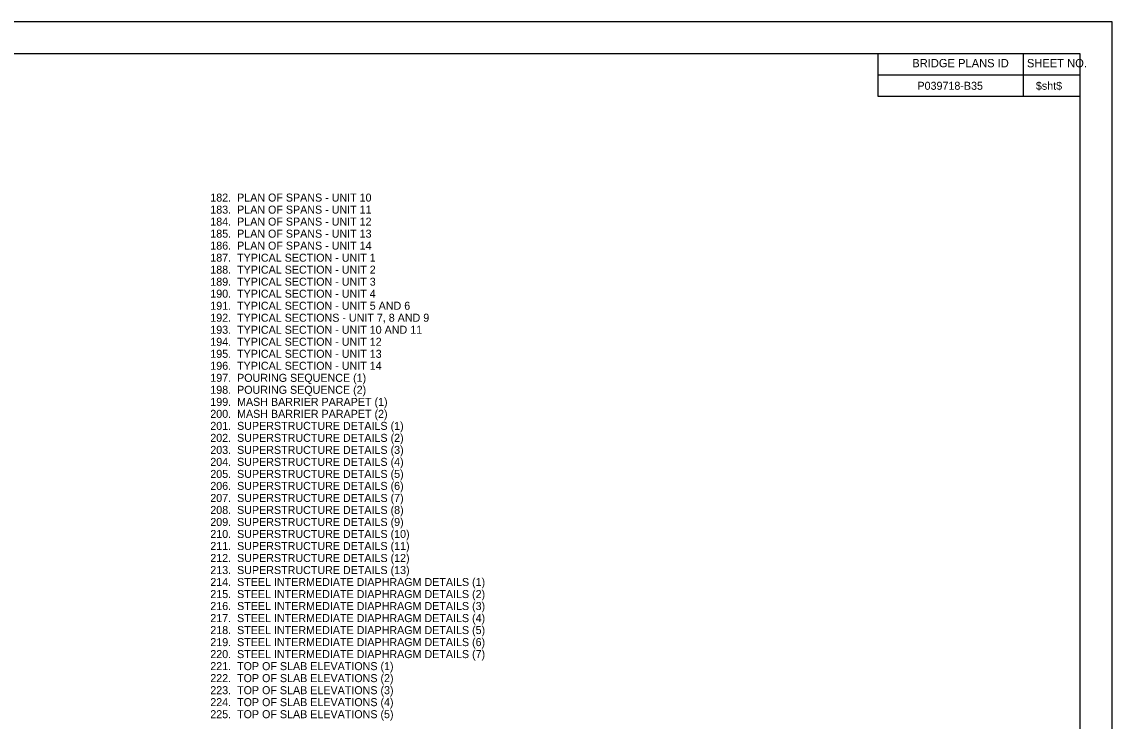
# Model space of a CAD drawing. Extents: x -125.5 to -89.4, y -5.1 to 16.9.
# Drawn here: x -106.56 to -89.53, y 6.02 to 16.93 of the extents above; entities that cross this region are included whole.
import ezdxf

# ---------------------------------------------------------------- set-up
doc = ezdxf.new("R2010")
doc.units = 0
for name, color, linetype in [('BR_BORDER LINES', 7, 'Continuous'), ('BR_TEXT', 7, 'Continuous'), ('Level 31', 7, 'Continuous')]:
    doc.layers.add(name, color=color, linetype=linetype)

msp = doc.modelspace()

# ---------------------------------------------------------------- linework, layer by layer
at = {"layer": 'BR_BORDER LINES'}
for p, q in [((-90.033, 16.434), (-123.699, 16.434)), ((-93.186, 15.767), (-93.186, 16.434)), ((-90.919, 15.767), (-90.919, 16.434)), ((-90.033, -4.566), (-90.033, 16.434)), ((-93.186, 16.104), (-90.033, 16.104)), ((-90.919, 16.104), (-90.033, 16.104)), ((-90.033, 15.767), (-93.186, 15.767))]:
    msp.add_line(p, q, dxfattribs=at)
at = {"layer": 'Level 31'}
msp.add_lwpolyline([(-125.533, -5.066), (-89.533, -5.066), (-89.533, 16.934), (-125.533, 16.934)], close=True, dxfattribs=at)

# ---------------------------------------------------------------- texts
at = {"layer": 'BR_TEXT'}
for s, height, p in [('BRIDGE PLANS ID', 0.13, (-92.654, 16.224)), ('SHEET NO.', 0.13, (-90.864, 16.224)), ('$sht$', 0.125, (-90.724, 15.873)), ('P039718-B35', 0.125, (-92.573, 15.873)), ('P039718-B35', 0.125, (-92.573, 15.873)), ('182.  PLAN OF SPANS - UNIT 10', 0.125, (-103.614, 14.128)), ('183.  PLAN OF SPANS - UNIT 11', 0.125, (-103.614, 13.94)), ('184.  PLAN OF SPANS - UNIT 12', 0.125, (-103.614, 13.753)), ('185.  PLAN OF SPANS - UNIT 13', 0.125, (-103.614, 13.565)), ('186.  PLAN OF SPANS - UNIT 14', 0.125, (-103.614, 13.378)), ('187.  TYPICAL SECTION - UNIT 1', 0.125, (-103.614, 13.19)), ('188.  TYPICAL SECTION - UNIT 2', 0.125, (-103.614, 13.003)), ('189.  TYPICAL SECTION - UNIT 3', 0.125, (-103.614, 12.815)), ('190.  TYPICAL SECTION - UNIT 4', 0.125, (-103.614, 12.628)), ('191.  TYPICAL SECTION - UNIT 5 AND 6', 0.125, (-103.614, 12.44)), ('192.  TYPICAL SECTIONS - UNIT 7, 8 AND 9', 0.125, (-103.614, 12.253)), ('193.  TYPICAL SECTION - UNIT 10 AND 11', 0.125, (-103.614, 12.065)), ('194.  TYPICAL SECTION - UNIT 12', 0.125, (-103.614, 11.878)), ('195.  TYPICAL SECTION - UNIT 13', 0.125, (-103.614, 11.69)), ('196.  TYPICAL SECTION - UNIT 14', 0.125, (-103.614, 11.503)), ('197.  POURING SEQUENCE (1)', 0.125, (-103.614, 11.315)), ('198.  POURING SEQUENCE (2)', 0.125, (-103.614, 11.128)), ('199.  MASH BARRIER PARAPET (1)', 0.125, (-103.614, 10.94)), ('200.  MASH BARRIER PARAPET (2)', 0.125, (-103.614, 10.753)), ('201.  SUPERSTRUCTURE DETAILS (1)', 0.125, (-103.614, 10.565)), ('202.  SUPERSTRUCTURE DETAILS (2)', 0.125, (-103.614, 10.378)), ('203.  SUPERSTRUCTURE DETAILS (3)', 0.125, (-103.614, 10.19)), ('204.  SUPERSTRUCTURE DETAILS (4)', 0.125, (-103.614, 10.003)), ('205.  SUPERSTRUCTURE DETAILS (5)', 0.125, (-103.614, 9.815)), ('206.  SUPERSTRUCTURE DETAILS (6)', 0.125, (-103.614, 9.628)), ('207.  SUPERSTRUCTURE DETAILS (7)', 0.125, (-103.614, 9.44)), ('208.  SUPERSTRUCTURE DETAILS (8)', 0.125, (-103.614, 9.253)), ('209.  SUPERSTRUCTURE DETAILS (9)', 0.125, (-103.614, 9.065)), ('210.  SUPERSTRUCTURE DETAILS (10)', 0.125, (-103.614, 8.878)), ('211.  SUPERSTRUCTURE DETAILS (11)', 0.125, (-103.614, 8.69)), ('212.  SUPERSTRUCTURE DETAILS (12)', 0.125, (-103.614, 8.503)), ('213.  SUPERSTRUCTURE DETAILS (13)', 0.125, (-103.614, 8.315)), ('214.  STEEL INTERMEDIATE DIAPHRAGM DETAILS (1)', 0.125, (-103.614, 8.128)), ('215.  STEEL INTERMEDIATE DIAPHRAGM DETAILS (2)', 0.125, (-103.614, 7.94)), ('216.  STEEL INTERMEDIATE DIAPHRAGM DETAILS (3)', 0.125, (-103.614, 7.753)), ('217.  STEEL INTERMEDIATE DIAPHRAGM DETAILS (4)', 0.125, (-103.614, 7.565)), ('218.  STEEL INTERMEDIATE DIAPHRAGM DETAILS (5)', 0.125, (-103.614, 7.378)), ('219.  STEEL INTERMEDIATE DIAPHRAGM DETAILS (6)', 0.125, (-103.614, 7.19)), ('220.  STEEL INTERMEDIATE DIAPHRAGM DETAILS (7)', 0.125, (-103.614, 7.003)), ('221.  TOP OF SLAB ELEVATIONS (1)', 0.125, (-103.614, 6.815)), ('222.  TOP OF SLAB ELEVATIONS (2)', 0.125, (-103.614, 6.628)), ('223.  TOP OF SLAB ELEVATIONS (3)', 0.125, (-103.614, 6.44)), ('224.  TOP OF SLAB ELEVATIONS (4)', 0.125, (-103.614, 6.253)), ('225.  TOP OF SLAB ELEVATIONS (5)', 0.125, (-103.614, 6.065))]:
    msp.add_text(s, height=height, dxfattribs=at).set_placement(p)

doc.saveas('drawing.dxf')
